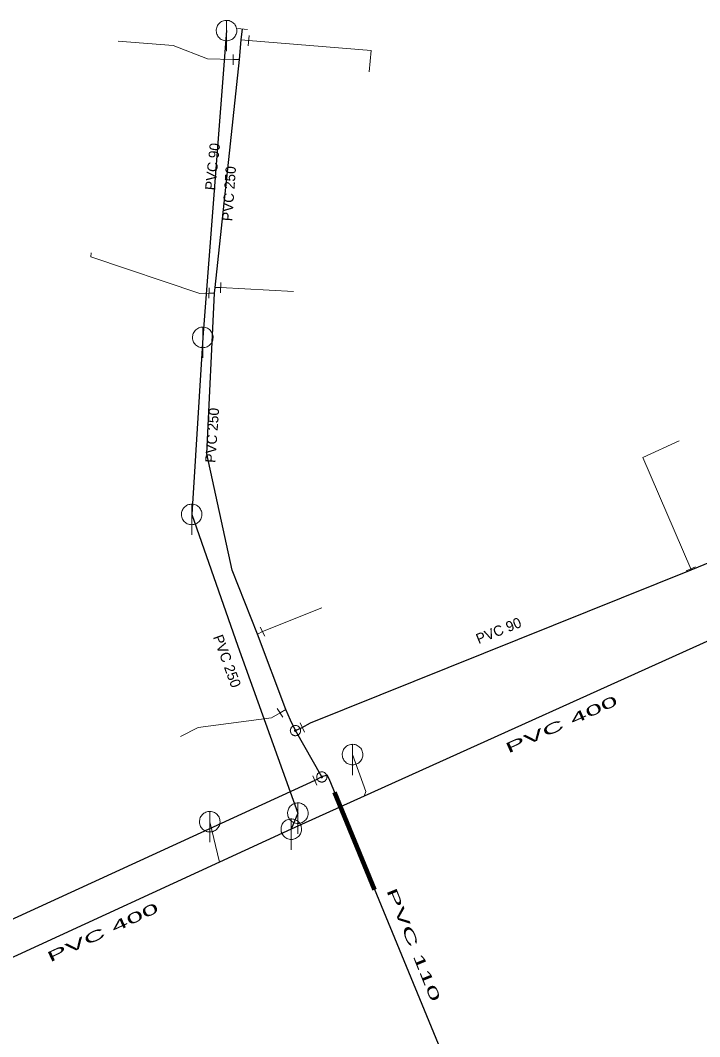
# Model space of a CAD drawing. Extents: x -659250 to -657316, y -997555 to -993684.
# Drawn here: x -657849.9 to -657783.8, y -996267.1 to -996168.1 of the extents above; entities that cross this region are included whole.
import ezdxf

# ---------------------------------------------------------------- set-up
doc = ezdxf.new("R2010")
doc.units = 0
doc.header["$LTSCALE"] = 0.4
doc.layers.add('1', color=7, linetype='Continuous')
for name, color, linetype, lineweight in [('11', 7, 'Continuous', 13), ('13', 7, 'Continuous', 13), ('14', 7, 'Continuous', 25), ('17', 7, 'Continuous', 25), ('22', 7, 'Continuous', 13), ('3', 7, 'Continuous', 106), ('34', 7, 'Continuous', 13), ('47', 7, 'Continuous', 13)]:
    doc.layers.add(name, color=color, linetype=linetype, lineweight=lineweight)

msp = doc.modelspace()

# ---------------------------------------------------------------- linework, layer by layer
at = {"layer": '11'}
msp.add_line((-657831.43, -996246.14), (-657830.495, -996250.089), dxfattribs=at)
msp.add_lwpolyline([(-657817.539, -996239.61), (-657816.26, -996243.21), (-657816.403, -996243.664)], dxfattribs=at)
at = {"layer": '13'}
for p, q in [((-657828.368, -996170.061), (-657827.652, -996170.122)), ((-657828.546, -996171.967), (-657829.142, -996171.967)), ((-657830.96, -996194.712), (-657831.495, -996194.696)), ((-657824.045, -996235.208), (-657824.596, -996235.555))]:
    msp.add_line(p, q, dxfattribs=at)
for points in [[(-657829.142, -996171.967), (-657831.646, -996171.909), (-657834.982, -996170.598), (-657840.346, -996170.181)], [(-657827.652, -996170.122), (-657815.732, -996171.074), (-657815.912, -996173.159)], [(-657831.495, -996194.696), (-657832.392, -996194.728), (-657843.002, -996191.153), (-657842.969, -996190.789)], [(-657830.901, -996194.151), (-657830.382, -996194.166), (-657823.284, -996194.539)], [(-657784.635, -996221.531), (-657789.289, -996210.692), (-657785.774, -996209.085)], [(-657826.787, -996227.886), (-657826.31, -996227.646), (-657820.526, -996225.326)], [(-657824.596, -996235.555), (-657825.416, -996236.041), (-657832.552, -996236.963), (-657834.281, -996237.857)]]:
    msp.add_lwpolyline(points, dxfattribs=at)
at = {"layer": '14'}
for p, q in [((-657829.8, -996169.149), (-657832.109, -996199.01)), ((-657832.109, -996199.01), (-657833.19, -996216.239)), ((-657822.859, -996245.309), (-657823.5, -996246.87))]:
    msp.add_line(p, q, dxfattribs=at)
at = {"layer": '14', "lineweight": 13}
msp.add_line((-657784.598, -996221.628), (-657784.635, -996221.531), dxfattribs=at)
at = {"layer": '14'}
for points in [[(-657833.19, -996216.239), (-657828.711, -996229.047), (-657822.859, -996245.309)], [(-657776.55, -996225.66), (-657780.76, -996227.561), (-657816.403, -996243.664), (-657823.5, -996246.87)], [(-657823.5, -996246.87), (-657830.495, -996250.089), (-657865.73, -996266.3)]]:
    msp.add_lwpolyline(points, dxfattribs=at)
at = {"layer": '17'}
for p, q in [((-657823.094, -996237.276), (-657822.434, -996236.967)), ((-657820.53, -996241.785), (-657823.094, -996237.276)), ((-657821.213, -996242.14), (-657950.917, -996301.638)), ((-657820.53, -996241.785), (-657821.213, -996242.14))]:
    msp.add_line(p, q, dxfattribs=at)
for points in [[(-657823.094, -996237.276), (-657823.585, -996236.269), (-657824.045, -996235.208), (-657826.787, -996227.886), (-657829.259, -996221.677), (-657831.702, -996210.337), (-657830.96, -996194.712), (-657830.901, -996194.151), (-657828.546, -996171.967), (-657828.368, -996170.061), (-657828.248, -996168.989)], [(-657822.434, -996236.967), (-657821.62, -996236.52), (-657784.598, -996221.628), (-657782.637, -996220.807)], [(-657807.881, -996270.934), (-657819.82, -996241.96), (-657819.998, -996241.603), (-657820.53, -996241.785)]]:
    msp.add_lwpolyline(points, dxfattribs=at)
at = {"layer": '22'}
for p, q in [((-657829.8, -996171.149), (-657829.799, -996168.149)), ((-657832.11, -996201.01), (-657832.109, -996198.01)), ((-657833.19, -996218.239), (-657833.189, -996215.239)), ((-657817.539, -996241.61), (-657817.538, -996238.61)), ((-657822.859, -996247.309), (-657822.858, -996244.309)), ((-657831.43, -996248.14), (-657831.429, -996245.14)), ((-657823.5, -996248.87), (-657823.499, -996245.87))]:
    msp.add_line(p, q, dxfattribs=at)
for points in [[(-657828.8, -996169.149), (-657828.805, -996169.04), (-657828.823, -996168.932), (-657828.853, -996168.826), (-657828.893, -996168.725), (-657828.945, -996168.628), (-657829.007, -996168.538), (-657829.079, -996168.455), (-657829.159, -996168.381), (-657829.247, -996168.315), (-657829.341, -996168.26), (-657829.441, -996168.215), (-657829.546, -996168.182), (-657829.653, -996168.16), (-657829.762, -996168.15), (-657829.872, -996168.152), (-657829.98, -996168.166), (-657830.087, -996168.191), (-657830.19, -996168.228), (-657830.288, -996168.277), (-657830.38, -996168.335), (-657830.466, -996168.404), (-657830.543, -996168.481), (-657830.612, -996168.567), (-657830.671, -996168.659), (-657830.719, -996168.757), (-657830.756, -996168.86), (-657830.782, -996168.967), (-657830.796, -996169.075), (-657830.799, -996169.185), (-657830.789, -996169.294), (-657830.768, -996169.401), (-657830.734, -996169.505), (-657830.69, -996169.605), (-657830.635, -996169.7), (-657830.569, -996169.788), (-657830.495, -996169.868), (-657830.412, -996169.94), (-657830.322, -996170.002), (-657830.226, -996170.054), (-657830.124, -996170.095), (-657830.019, -996170.125), (-657829.911, -996170.143), (-657829.801, -996170.149), (-657829.692, -996170.143), (-657829.584, -996170.125), (-657829.479, -996170.096), (-657829.377, -996170.055), (-657829.28, -996170.003), (-657829.19, -996169.941), (-657829.107, -996169.87), (-657829.032, -996169.79), (-657828.967, -996169.702), (-657828.911, -996169.608), (-657828.867, -996169.508), (-657828.833, -996169.404), (-657828.811, -996169.296), (-657828.801, -996169.187)], [(-657831.11, -996199.01), (-657831.115, -996198.901), (-657831.133, -996198.793), (-657831.163, -996198.687), (-657831.203, -996198.586), (-657831.255, -996198.489), (-657831.317, -996198.399), (-657831.389, -996198.316), (-657831.469, -996198.242), (-657831.557, -996198.176), (-657831.651, -996198.121), (-657831.751, -996198.076), (-657831.856, -996198.043), (-657831.963, -996198.021), (-657832.072, -996198.011), (-657832.182, -996198.013), (-657832.29, -996198.027), (-657832.397, -996198.052), (-657832.5, -996198.089), (-657832.598, -996198.138), (-657832.69, -996198.196), (-657832.776, -996198.265), (-657832.853, -996198.342), (-657832.922, -996198.428), (-657832.981, -996198.52), (-657833.029, -996198.618), (-657833.066, -996198.721), (-657833.092, -996198.828), (-657833.106, -996198.936), (-657833.109, -996199.046), (-657833.099, -996199.155), (-657833.078, -996199.262), (-657833.044, -996199.366), (-657833, -996199.466), (-657832.945, -996199.561), (-657832.879, -996199.649), (-657832.805, -996199.729), (-657832.722, -996199.801), (-657832.632, -996199.863), (-657832.536, -996199.915), (-657832.434, -996199.956), (-657832.329, -996199.986), (-657832.221, -996200.004), (-657832.111, -996200.01), (-657832.002, -996200.004), (-657831.894, -996199.986), (-657831.789, -996199.957), (-657831.687, -996199.916), (-657831.59, -996199.864), (-657831.5, -996199.802), (-657831.417, -996199.731), (-657831.342, -996199.651), (-657831.277, -996199.563), (-657831.221, -996199.469), (-657831.177, -996199.369), (-657831.143, -996199.265), (-657831.121, -996199.157), (-657831.111, -996199.048)], [(-657832.19, -996216.239), (-657832.195, -996216.13), (-657832.213, -996216.022), (-657832.243, -996215.916), (-657832.283, -996215.815), (-657832.335, -996215.718), (-657832.397, -996215.628), (-657832.469, -996215.545), (-657832.549, -996215.471), (-657832.637, -996215.405), (-657832.731, -996215.35), (-657832.831, -996215.305), (-657832.936, -996215.272), (-657833.043, -996215.25), (-657833.152, -996215.24), (-657833.262, -996215.242), (-657833.37, -996215.256), (-657833.477, -996215.281), (-657833.58, -996215.318), (-657833.678, -996215.367), (-657833.77, -996215.425), (-657833.856, -996215.494), (-657833.933, -996215.571), (-657834.002, -996215.657), (-657834.061, -996215.749), (-657834.109, -996215.847), (-657834.146, -996215.95), (-657834.172, -996216.057), (-657834.186, -996216.165), (-657834.189, -996216.275), (-657834.179, -996216.384), (-657834.158, -996216.491), (-657834.124, -996216.595), (-657834.08, -996216.695), (-657834.025, -996216.79), (-657833.959, -996216.878), (-657833.885, -996216.958), (-657833.802, -996217.03), (-657833.712, -996217.092), (-657833.616, -996217.144), (-657833.514, -996217.185), (-657833.409, -996217.215), (-657833.301, -996217.233), (-657833.191, -996217.239), (-657833.082, -996217.233), (-657832.974, -996217.215), (-657832.869, -996217.186), (-657832.767, -996217.145), (-657832.67, -996217.093), (-657832.58, -996217.031), (-657832.497, -996216.96), (-657832.422, -996216.88), (-657832.357, -996216.792), (-657832.301, -996216.698), (-657832.257, -996216.598), (-657832.223, -996216.494), (-657832.201, -996216.386), (-657832.191, -996216.277)], [(-657816.539, -996239.61), (-657816.544, -996239.501), (-657816.562, -996239.393), (-657816.592, -996239.287), (-657816.632, -996239.186), (-657816.684, -996239.089), (-657816.746, -996238.999), (-657816.818, -996238.916), (-657816.898, -996238.842), (-657816.986, -996238.776), (-657817.08, -996238.721), (-657817.18, -996238.676), (-657817.285, -996238.643), (-657817.392, -996238.621), (-657817.501, -996238.611), (-657817.611, -996238.613), (-657817.719, -996238.627), (-657817.826, -996238.652), (-657817.929, -996238.689), (-657818.027, -996238.738), (-657818.119, -996238.796), (-657818.205, -996238.865), (-657818.282, -996238.942), (-657818.351, -996239.028), (-657818.41, -996239.12), (-657818.458, -996239.218), (-657818.495, -996239.321), (-657818.521, -996239.428), (-657818.535, -996239.536), (-657818.538, -996239.646), (-657818.528, -996239.755), (-657818.507, -996239.862), (-657818.473, -996239.966), (-657818.429, -996240.066), (-657818.374, -996240.161), (-657818.308, -996240.249), (-657818.234, -996240.329), (-657818.151, -996240.401), (-657818.061, -996240.463), (-657817.965, -996240.515), (-657817.863, -996240.556), (-657817.758, -996240.586), (-657817.65, -996240.604), (-657817.54, -996240.61), (-657817.431, -996240.604), (-657817.323, -996240.586), (-657817.218, -996240.557), (-657817.116, -996240.516), (-657817.019, -996240.464), (-657816.929, -996240.402), (-657816.846, -996240.331), (-657816.771, -996240.251), (-657816.706, -996240.163), (-657816.65, -996240.069), (-657816.606, -996239.969), (-657816.572, -996239.865), (-657816.55, -996239.757), (-657816.54, -996239.648)], [(-657821.859, -996245.309), (-657821.864, -996245.2), (-657821.882, -996245.092), (-657821.912, -996244.986), (-657821.952, -996244.885), (-657822.004, -996244.788), (-657822.066, -996244.698), (-657822.138, -996244.615), (-657822.218, -996244.541), (-657822.306, -996244.475), (-657822.4, -996244.42), (-657822.5, -996244.375), (-657822.605, -996244.342), (-657822.712, -996244.32), (-657822.821, -996244.31), (-657822.931, -996244.312), (-657823.039, -996244.326), (-657823.146, -996244.351), (-657823.249, -996244.388), (-657823.347, -996244.437), (-657823.439, -996244.495), (-657823.525, -996244.564), (-657823.602, -996244.641), (-657823.671, -996244.727), (-657823.73, -996244.819), (-657823.778, -996244.917), (-657823.815, -996245.02), (-657823.841, -996245.127), (-657823.855, -996245.235), (-657823.858, -996245.345), (-657823.848, -996245.454), (-657823.827, -996245.561), (-657823.793, -996245.665), (-657823.749, -996245.765), (-657823.694, -996245.86), (-657823.628, -996245.948), (-657823.554, -996246.028), (-657823.471, -996246.1), (-657823.381, -996246.162), (-657823.285, -996246.214), (-657823.183, -996246.255), (-657823.078, -996246.285), (-657822.97, -996246.303), (-657822.86, -996246.309), (-657822.751, -996246.303), (-657822.643, -996246.285), (-657822.538, -996246.256), (-657822.436, -996246.215), (-657822.339, -996246.163), (-657822.249, -996246.101), (-657822.166, -996246.03), (-657822.091, -996245.95), (-657822.026, -996245.862), (-657821.97, -996245.768), (-657821.926, -996245.668), (-657821.892, -996245.564), (-657821.87, -996245.456), (-657821.86, -996245.347)], [(-657830.43, -996246.14), (-657830.435, -996246.031), (-657830.453, -996245.923), (-657830.483, -996245.817), (-657830.523, -996245.716), (-657830.575, -996245.619), (-657830.637, -996245.529), (-657830.709, -996245.446), (-657830.789, -996245.372), (-657830.877, -996245.306), (-657830.971, -996245.251), (-657831.071, -996245.206), (-657831.176, -996245.173), (-657831.283, -996245.151), (-657831.392, -996245.141), (-657831.502, -996245.143), (-657831.61, -996245.157), (-657831.717, -996245.182), (-657831.82, -996245.219), (-657831.918, -996245.268), (-657832.01, -996245.326), (-657832.096, -996245.395), (-657832.173, -996245.472), (-657832.242, -996245.558), (-657832.301, -996245.65), (-657832.349, -996245.748), (-657832.386, -996245.851), (-657832.412, -996245.958), (-657832.426, -996246.066), (-657832.429, -996246.176), (-657832.419, -996246.285), (-657832.398, -996246.392), (-657832.364, -996246.496), (-657832.32, -996246.596), (-657832.265, -996246.691), (-657832.199, -996246.779), (-657832.125, -996246.859), (-657832.042, -996246.931), (-657831.952, -996246.993), (-657831.856, -996247.045), (-657831.754, -996247.086), (-657831.649, -996247.116), (-657831.541, -996247.134), (-657831.431, -996247.14), (-657831.322, -996247.134), (-657831.214, -996247.116), (-657831.109, -996247.087), (-657831.007, -996247.046), (-657830.91, -996246.994), (-657830.82, -996246.932), (-657830.737, -996246.861), (-657830.662, -996246.781), (-657830.597, -996246.693), (-657830.541, -996246.599), (-657830.497, -996246.499), (-657830.463, -996246.395), (-657830.441, -996246.287), (-657830.431, -996246.178)], [(-657822.5, -996246.87), (-657822.505, -996246.761), (-657822.523, -996246.653), (-657822.553, -996246.547), (-657822.593, -996246.446), (-657822.645, -996246.349), (-657822.707, -996246.259), (-657822.779, -996246.176), (-657822.859, -996246.102), (-657822.947, -996246.036), (-657823.041, -996245.981), (-657823.141, -996245.936), (-657823.246, -996245.903), (-657823.353, -996245.881), (-657823.462, -996245.871), (-657823.572, -996245.873), (-657823.68, -996245.887), (-657823.787, -996245.912), (-657823.89, -996245.949), (-657823.988, -996245.998), (-657824.08, -996246.056), (-657824.166, -996246.125), (-657824.243, -996246.202), (-657824.312, -996246.288), (-657824.371, -996246.38), (-657824.419, -996246.478), (-657824.456, -996246.581), (-657824.482, -996246.688), (-657824.496, -996246.796), (-657824.499, -996246.906), (-657824.489, -996247.015), (-657824.468, -996247.122), (-657824.434, -996247.226), (-657824.39, -996247.326), (-657824.335, -996247.421), (-657824.269, -996247.509), (-657824.195, -996247.589), (-657824.112, -996247.661), (-657824.022, -996247.723), (-657823.926, -996247.775), (-657823.824, -996247.816), (-657823.719, -996247.846), (-657823.611, -996247.864), (-657823.501, -996247.87), (-657823.392, -996247.864), (-657823.284, -996247.846), (-657823.179, -996247.817), (-657823.077, -996247.776), (-657822.98, -996247.724), (-657822.89, -996247.662), (-657822.807, -996247.591), (-657822.732, -996247.511), (-657822.667, -996247.423), (-657822.611, -996247.329), (-657822.567, -996247.229), (-657822.533, -996247.125), (-657822.511, -996247.017), (-657822.501, -996246.908)]]:
    msp.add_lwpolyline(points, close=True, dxfattribs=at)
at = {"layer": '3'}
msp.add_line((-657815.397, -996252.783), (-657819.311, -996243.309), dxfattribs=at)
at = {"layer": '3', "lineweight": 100}
msp.add_line((-657815.397, -996252.783), (-657819.311, -996243.309), dxfattribs=at)
at = {"layer": '34'}
for p, q in [((-657828.745, -996168.934), (-657827.751, -996169.044)), ((-657827.597, -996169.624), (-657827.707, -996170.618)), ((-657829.142, -996171.467), (-657829.142, -996172.467)), ((-657831.481, -996194.196), (-657831.509, -996195.195)), ((-657830.368, -996193.666), (-657830.396, -996194.665)), ((-657784.17, -996221.345), (-657785.099, -996221.715)), ((-657826.534, -996227.199), (-657826.086, -996228.093)), ((-657824.862, -996235.131), (-657824.33, -996235.978)), ((-657822.646, -996236.514), (-657822.222, -996237.42)), ((-657821.419, -996241.684), (-657821.007, -996242.595))]:
    msp.add_line(p, q, dxfattribs=at)
at = {"layer": '47'}
for points in [[(-657822.594, -996237.277), (-657822.597, -996237.225), (-657822.605, -996237.173), (-657822.619, -996237.123), (-657822.637, -996237.074), (-657822.661, -996237.027), (-657822.69, -996236.983), (-657822.723, -996236.943), (-657822.76, -996236.906), (-657822.8, -996236.873), (-657822.844, -996236.844), (-657822.891, -996236.82), (-657822.94, -996236.802), (-657822.99, -996236.788), (-657823.042, -996236.78), (-657823.094, -996236.777), (-657823.146, -996236.78), (-657823.198, -996236.788), (-657823.249, -996236.802), (-657823.297, -996236.82), (-657823.344, -996236.844), (-657823.388, -996236.873), (-657823.429, -996236.906), (-657823.466, -996236.943), (-657823.499, -996236.983), (-657823.527, -996237.027), (-657823.551, -996237.074), (-657823.57, -996237.123), (-657823.583, -996237.173), (-657823.591, -996237.225), (-657823.594, -996237.277), (-657823.591, -996237.329), (-657823.583, -996237.381), (-657823.57, -996237.432), (-657823.551, -996237.48), (-657823.527, -996237.527), (-657823.499, -996237.571), (-657823.466, -996237.612), (-657823.429, -996237.649), (-657823.388, -996237.682), (-657823.344, -996237.71), (-657823.297, -996237.734), (-657823.249, -996237.753), (-657823.198, -996237.766), (-657823.146, -996237.774), (-657823.094, -996237.777), (-657823.042, -996237.774), (-657822.99, -996237.766), (-657822.94, -996237.753), (-657822.891, -996237.734), (-657822.844, -996237.71), (-657822.8, -996237.682), (-657822.76, -996237.649), (-657822.723, -996237.612), (-657822.69, -996237.571), (-657822.661, -996237.527), (-657822.637, -996237.48), (-657822.619, -996237.432), (-657822.605, -996237.381), (-657822.597, -996237.329)], [(-657823.012, -996237.277), (-657823.012, -996237.268), (-657823.014, -996237.26), (-657823.016, -996237.252), (-657823.019, -996237.244), (-657823.023, -996237.236), (-657823.028, -996237.229), (-657823.033, -996237.222), (-657823.039, -996237.216), (-657823.046, -996237.211), (-657823.053, -996237.206), (-657823.061, -996237.202), (-657823.069, -996237.199), (-657823.077, -996237.197), (-657823.085, -996237.195), (-657823.094, -996237.195), (-657823.103, -996237.195), (-657823.111, -996237.197), (-657823.119, -996237.199), (-657823.127, -996237.202), (-657823.135, -996237.206), (-657823.142, -996237.211), (-657823.149, -996237.216), (-657823.155, -996237.222), (-657823.161, -996237.229), (-657823.165, -996237.236), (-657823.169, -996237.244), (-657823.172, -996237.252), (-657823.174, -996237.26), (-657823.176, -996237.268), (-657823.176, -996237.277), (-657823.176, -996237.286), (-657823.174, -996237.294), (-657823.172, -996237.302), (-657823.169, -996237.31), (-657823.165, -996237.318), (-657823.161, -996237.325), (-657823.155, -996237.332), (-657823.149, -996237.338), (-657823.142, -996237.344), (-657823.135, -996237.348), (-657823.127, -996237.352), (-657823.119, -996237.355), (-657823.111, -996237.357), (-657823.103, -996237.359), (-657823.094, -996237.359), (-657823.085, -996237.359), (-657823.077, -996237.357), (-657823.069, -996237.355), (-657823.061, -996237.352), (-657823.053, -996237.348), (-657823.046, -996237.344), (-657823.039, -996237.338), (-657823.033, -996237.332), (-657823.028, -996237.325), (-657823.023, -996237.318), (-657823.019, -996237.31), (-657823.016, -996237.302), (-657823.014, -996237.294), (-657823.012, -996237.286)], [(-657820.03, -996241.786), (-657820.033, -996241.733), (-657820.041, -996241.681), (-657820.055, -996241.632), (-657820.073, -996241.583), (-657820.097, -996241.536), (-657820.126, -996241.492), (-657820.159, -996241.451), (-657820.196, -996241.414), (-657820.236, -996241.382), (-657820.28, -996241.353), (-657820.327, -996241.328), (-657820.376, -996241.311), (-657820.426, -996241.297), (-657820.478, -996241.289), (-657820.53, -996241.286), (-657820.582, -996241.289), (-657820.634, -996241.297), (-657820.685, -996241.311), (-657820.733, -996241.328), (-657820.78, -996241.353), (-657820.824, -996241.382), (-657820.865, -996241.414), (-657820.902, -996241.451), (-657820.935, -996241.492), (-657820.963, -996241.536), (-657820.987, -996241.583), (-657821.006, -996241.632), (-657821.019, -996241.681), (-657821.027, -996241.733), (-657821.03, -996241.786), (-657821.027, -996241.838), (-657821.019, -996241.89), (-657821.006, -996241.941), (-657820.987, -996241.989), (-657820.963, -996242.036), (-657820.935, -996242.08), (-657820.902, -996242.12), (-657820.865, -996242.157), (-657820.824, -996242.191), (-657820.78, -996242.218), (-657820.733, -996242.243), (-657820.685, -996242.262), (-657820.634, -996242.274), (-657820.582, -996242.282), (-657820.53, -996242.286), (-657820.478, -996242.282), (-657820.426, -996242.274), (-657820.376, -996242.262), (-657820.327, -996242.243), (-657820.28, -996242.218), (-657820.236, -996242.191), (-657820.196, -996242.157), (-657820.159, -996242.12), (-657820.126, -996242.08), (-657820.097, -996242.036), (-657820.073, -996241.989), (-657820.055, -996241.941), (-657820.041, -996241.89), (-657820.033, -996241.838)], [(-657820.448, -996241.786), (-657820.448, -996241.777), (-657820.45, -996241.769), (-657820.452, -996241.761), (-657820.455, -996241.752), (-657820.459, -996241.745), (-657820.464, -996241.738), (-657820.469, -996241.73), (-657820.475, -996241.725), (-657820.482, -996241.72), (-657820.489, -996241.715), (-657820.497, -996241.711), (-657820.505, -996241.708), (-657820.513, -996241.706), (-657820.521, -996241.703), (-657820.53, -996241.703), (-657820.539, -996241.703), (-657820.547, -996241.706), (-657820.555, -996241.708), (-657820.563, -996241.711), (-657820.571, -996241.715), (-657820.578, -996241.72), (-657820.585, -996241.725), (-657820.591, -996241.73), (-657820.597, -996241.738), (-657820.601, -996241.745), (-657820.605, -996241.752), (-657820.608, -996241.761), (-657820.61, -996241.769), (-657820.612, -996241.777), (-657820.612, -996241.786), (-657820.612, -996241.794), (-657820.61, -996241.803), (-657820.608, -996241.811), (-657820.605, -996241.819), (-657820.601, -996241.826), (-657820.597, -996241.833), (-657820.591, -996241.841), (-657820.585, -996241.847), (-657820.578, -996241.853), (-657820.571, -996241.857), (-657820.563, -996241.86), (-657820.555, -996241.864), (-657820.547, -996241.865), (-657820.539, -996241.868), (-657820.53, -996241.868), (-657820.521, -996241.868), (-657820.513, -996241.865), (-657820.505, -996241.864), (-657820.497, -996241.86), (-657820.489, -996241.857), (-657820.482, -996241.853), (-657820.475, -996241.847), (-657820.469, -996241.841), (-657820.464, -996241.833), (-657820.459, -996241.826), (-657820.455, -996241.819), (-657820.452, -996241.811), (-657820.45, -996241.803), (-657820.448, -996241.794)]]:
    msp.add_lwpolyline(points, close=True, dxfattribs=at)

# ---------------------------------------------------------------- texts
at = {"layer": '1'}
for s, rotation, p in [('PVC 90', 84, (-657830.904, -996184.729)), ('PVC 250 ', 86, (-657829.245, -996187.722)), ('PVC 250 ', 86, (-657830.886, -996211.241)), ('PVC 90', 22, (-657805.279, -996228.871)), ('PVC 250 ', 290, (-657831.131, -996228.164))]:
    msp.add_text(s, height=1, rotation=rotation, dxfattribs=at).set_placement(p)
at = {"layer": '1', "width": 2.2}
for s, rotation, p in [('PVC 400 ', 24, (-657802.396, -996239.514)), ('PVC 110 ', 292, (-657814.272, -996252.835)), ('PVC 400 ', 25, (-657846.964, -996259.851))]:
    msp.add_text(s, height=1, rotation=rotation, dxfattribs=at).set_placement(p)

doc.saveas('drawing.dxf')
